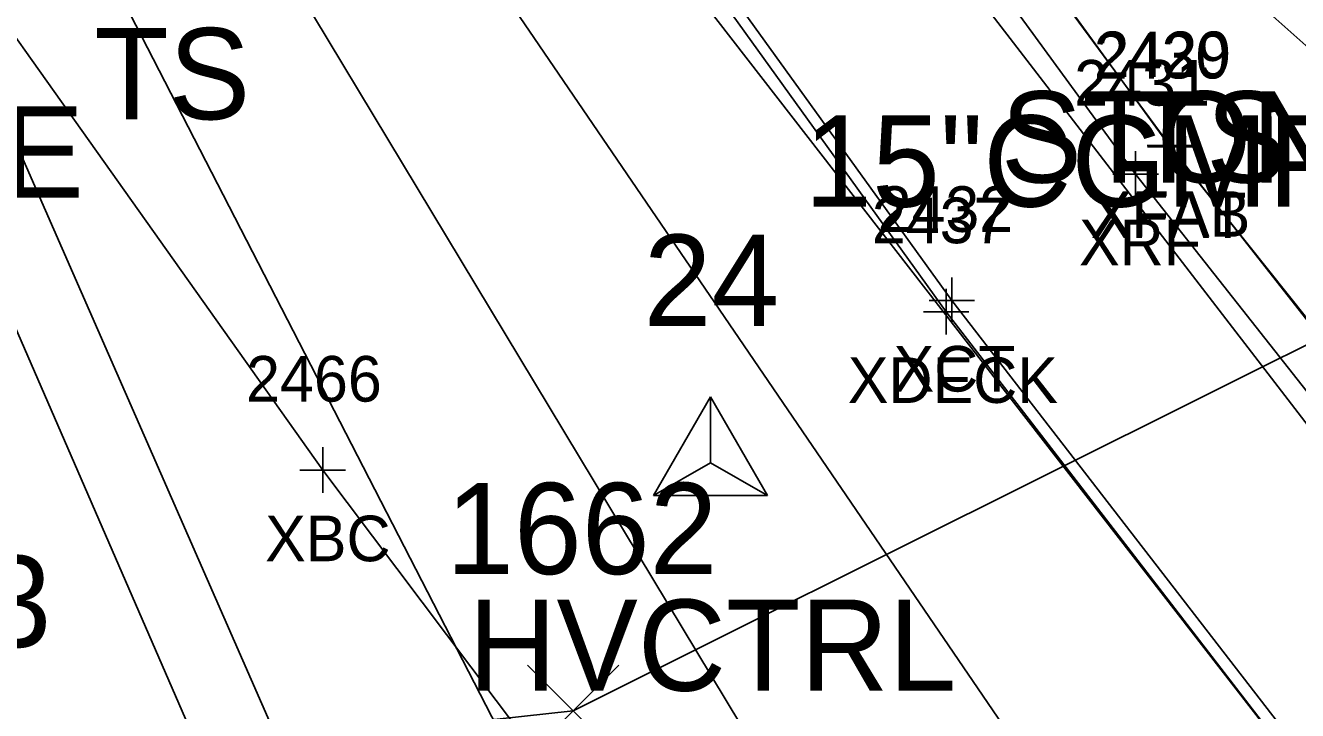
# Model space of a CAD drawing. Extents: x 1504228 to 1506103, y 437717 to 440106.
# Drawn here: x 1505206.79 to 1505234.68, y 438213.89 to 438228.91 of the extents above; entities that cross this region are included whole.
import ezdxf

# ---------------------------------------------------------------- set-up
doc = ezdxf.new("R2010")
doc.units = 0
for name, color, linetype in [('B_A', 7, 'Continuous'), ('B_I', 7, 'Continuous'), ('B_TIC', 7, 'Continuous'), ('BB', 7, 'Continuous'), ('BDC', 7, 'Continuous'), ('BELB', 7, 'Continuous'), ('BF', 7, 'Continuous'), ('BR', 7, 'Continuous'), ('C_A', 7, 'Continuous'), ('C_I', 7, 'Continuous'), ('CPSM', 7, 'Continuous'), ('D_C', 7, 'Continuous'), ('L_A', 7, 'Continuous'), ('L_I', 7, 'Continuous'), ('L_TIC', 7, 'Continuous'), ('LASF', 7, 'Continuous'), ('LELB', 7, 'Continuous')]:
    doc.layers.add(name, color=color, linetype=linetype)

msp = doc.modelspace()

# ---------------------------------------------------------------- linework, layer by layer
at = {"layer": 'B_TIC'}
for p, q in [((1505231.88, 438226.273), (1505231.956, 438226.273)), ((1505231.887, 438226.243), (1505231.962, 438226.243)), ((1505231.128, 438225.649), (1505231.204, 438225.649)), ((1505227.1, 438222.88), (1505227.175, 438222.88)), ((1505226.976, 438222.631), (1505227.051, 438222.631)), ((1505213.309, 438219.16), (1505213.385, 438219.16))]:
    msp.add_line(p, q, dxfattribs=at)
for points in [[(1505231.877, 438225.773), (1505231.877, 438226.773)], [(1505231.883, 438225.743), (1505231.883, 438226.743)], [(1505231.377, 438226.273), (1505232.377, 438226.273)], [(1505231.383, 438226.243), (1505232.383, 438226.243)], [(1505231.125, 438225.149), (1505231.125, 438226.149)], [(1505230.625, 438225.649), (1505231.625, 438225.649)], [(1505227.096, 438222.38), (1505227.096, 438223.38)], [(1505226.596, 438222.88), (1505227.596, 438222.88)], [(1505226.972, 438222.131), (1505226.972, 438223.131)], [(1505226.472, 438222.631), (1505227.472, 438222.631)], [(1505213.306, 438218.66), (1505213.306, 438219.66)], [(1505212.806, 438219.16), (1505213.806, 438219.16)]]:
    msp.add_lwpolyline(points, dxfattribs=at)
at = {"layer": 'BB'}
for points in [[(1505216.867, 438243.586), (1505244.83, 438207.228)], [(1505212.21, 438241.584), (1505240.46, 438205.162)], [(1505209.818, 438240.537), (1505235.468, 438202.936)], [(1505206.972, 438239.295), (1505230.232, 438200.699)], [(1505204.463, 438238.12), (1505224.942, 438198.346)], [(1505201.879, 438237.041), (1505219.842, 438196.087)], [(1505200.413, 438236.44), (1505218.276, 438195.351)]]:
    msp.add_lwpolyline(points, dxfattribs=at)
at = {"layer": 'BDC'}
msp.add_lwpolyline([(1505211.925, 438243.921), (1505227.096, 438222.88), (1505239.823, 438206.409), (1505253.849, 438189.887), (1505268.071, 438174.436), (1505276.686, 438165.513)], dxfattribs=at)
at = {"layer": 'BELB'}
for points in [[(1505211.812, 438243.704), (1505226.972, 438222.631), (1505239.63, 438206.209), (1505253.732, 438189.745), (1505267.938, 438174.29), (1505276.516, 438165.316)], [(1505262.808, 438159.474), (1505244.884, 438179.311), (1505229.042, 438198.247), (1505213.306, 438219.16), (1505200.113, 438237.757)]]:
    msp.add_lwpolyline(points, dxfattribs=at)
at = {"layer": 'BF'}
for points in [[(1505211.925, 438243.921), (1505216.347, 438245.376), (1505218.618, 438242.78), (1505219.411, 438243.379), (1505231.883, 438226.243), (1505244.785, 438210.059), (1505258.149, 438194.034), (1505272.082, 438178.605), (1505279.641, 438170.867), (1505278.911, 438170.024), (1505281.091, 438167.856), (1505276.686, 438165.513)], [(1505219.325, 438243.288), (1505231.877, 438226.273), (1505244.695, 438209.964), (1505258.118, 438194.019), (1505272.126, 438178.595), (1505280.957, 438169.659)]]:
    msp.add_lwpolyline(points, dxfattribs=at)
at = {"layer": 'BR'}
msp.add_lwpolyline([(1505218.618, 438242.78), (1505231.125, 438225.649), (1505244.017, 438209.29), (1505257.36, 438193.318), (1505271.307, 438177.817), (1505278.911, 438170.024)], dxfattribs=at)
at = {"layer": 'CPSM'}
for p, q in [((1505220.555, 438218.599), (1505221.805, 438220.765)), ((1505223.055, 438218.599), (1505221.805, 438220.765)), ((1505221.806, 438219.321), (1505221.805, 438220.765)), ((1505220.555, 438218.599), (1505221.806, 438219.321)), ((1505221.806, 438219.321), (1505221.806, 438219.321)), ((1505221.806, 438219.321), (1505223.055, 438218.599)), ((1505220.555, 438218.599), (1505223.055, 438218.599))]:
    msp.add_line(p, q, dxfattribs=at)
at = {"layer": 'L_TIC'}
for points in [[(1505217.796, 438212.879), (1505219.796, 438214.879)], [(1505219.796, 438212.879), (1505217.796, 438214.879)]]:
    msp.add_lwpolyline(points, dxfattribs=at)
at = {"layer": 'LASF'}
msp.add_lwpolyline([(1505231.536, 438240.553), (1505235.748, 438236.802), (1505232.624, 438230.462), (1505239.591, 438224.256), (1505247.096, 438215.294), (1505232.375, 438208.772), (1505219.716, 438203.952), (1505216.343, 438201.336), (1505195.139, 438190.329), (1505194.762, 438205.795)], dxfattribs=at)
at = {"layer": 'LELB'}
msp.add_lwpolyline([(1505270.798, 438231.377), (1505256.305, 438221.751), (1505239.591, 438224.256), (1505218.796, 438213.879), (1505204.191, 438212.28), (1505197.941, 438215.08), (1505180.455, 438206.428)], dxfattribs=at)

# ---------------------------------------------------------------- texts
at = {"layer": 'B_A'}
for s, p in [('XFAT', (1505230.139, 438224.243)), ('XFAB', (1505230.148, 438224.273)), ('XRF', (1505229.885, 438223.649)), ('XCT', (1505225.817, 438220.88)), ('XDECK', (1505224.815, 438220.631)), ('XBC', (1505212.042, 438217.16))]:
    msp.add_text(s, height=1, dxfattribs=at).set_placement(p)
at = {"layer": 'B_I'}
for s, p in [('2430', (1505230.21, 438227.743)), ('2429', (1505230.243, 438227.773)), ('2431', (1505229.778, 438227.149)), ('2432', (1505225.467, 438224.38)), ('2437', (1505225.342, 438224.131)), ('2466', (1505211.625, 438220.66))]:
    msp.add_text(s, height=1, dxfattribs=at).set_placement(p)
at = {"layer": 'C_A'}
msp.add_text('HVCTRL', height=2, dxfattribs=at).set_placement((1505216.498, 438214.321))
at = {"layer": 'C_I'}
msp.add_text('24', height=2, dxfattribs=at).set_placement((1505220.341, 438222.321))
at = {"layer": 'D_C'}
msp.add_text('15"CGMP', height=2, dxfattribs=at).set_placement((1505223.86, 438224.934))
at = {"layer": 'L_A'}
for s, p in [('TS', (1505208.298, 438226.849)), ('STONE', (1505228.168, 438225.462)), ('TS', (1505231.034, 438225.462)), ('STONE', (1505198.856, 438225.133))]:
    msp.add_text(s, height=2, dxfattribs=at).set_placement(p)
at = {"layer": 'L_I'}
for s, p in [('1662', (1505216.009, 438216.879)), ('1663', (1505201.404, 438215.28))]:
    msp.add_text(s, height=2, dxfattribs=at).set_placement(p)

doc.saveas('drawing.dxf')
